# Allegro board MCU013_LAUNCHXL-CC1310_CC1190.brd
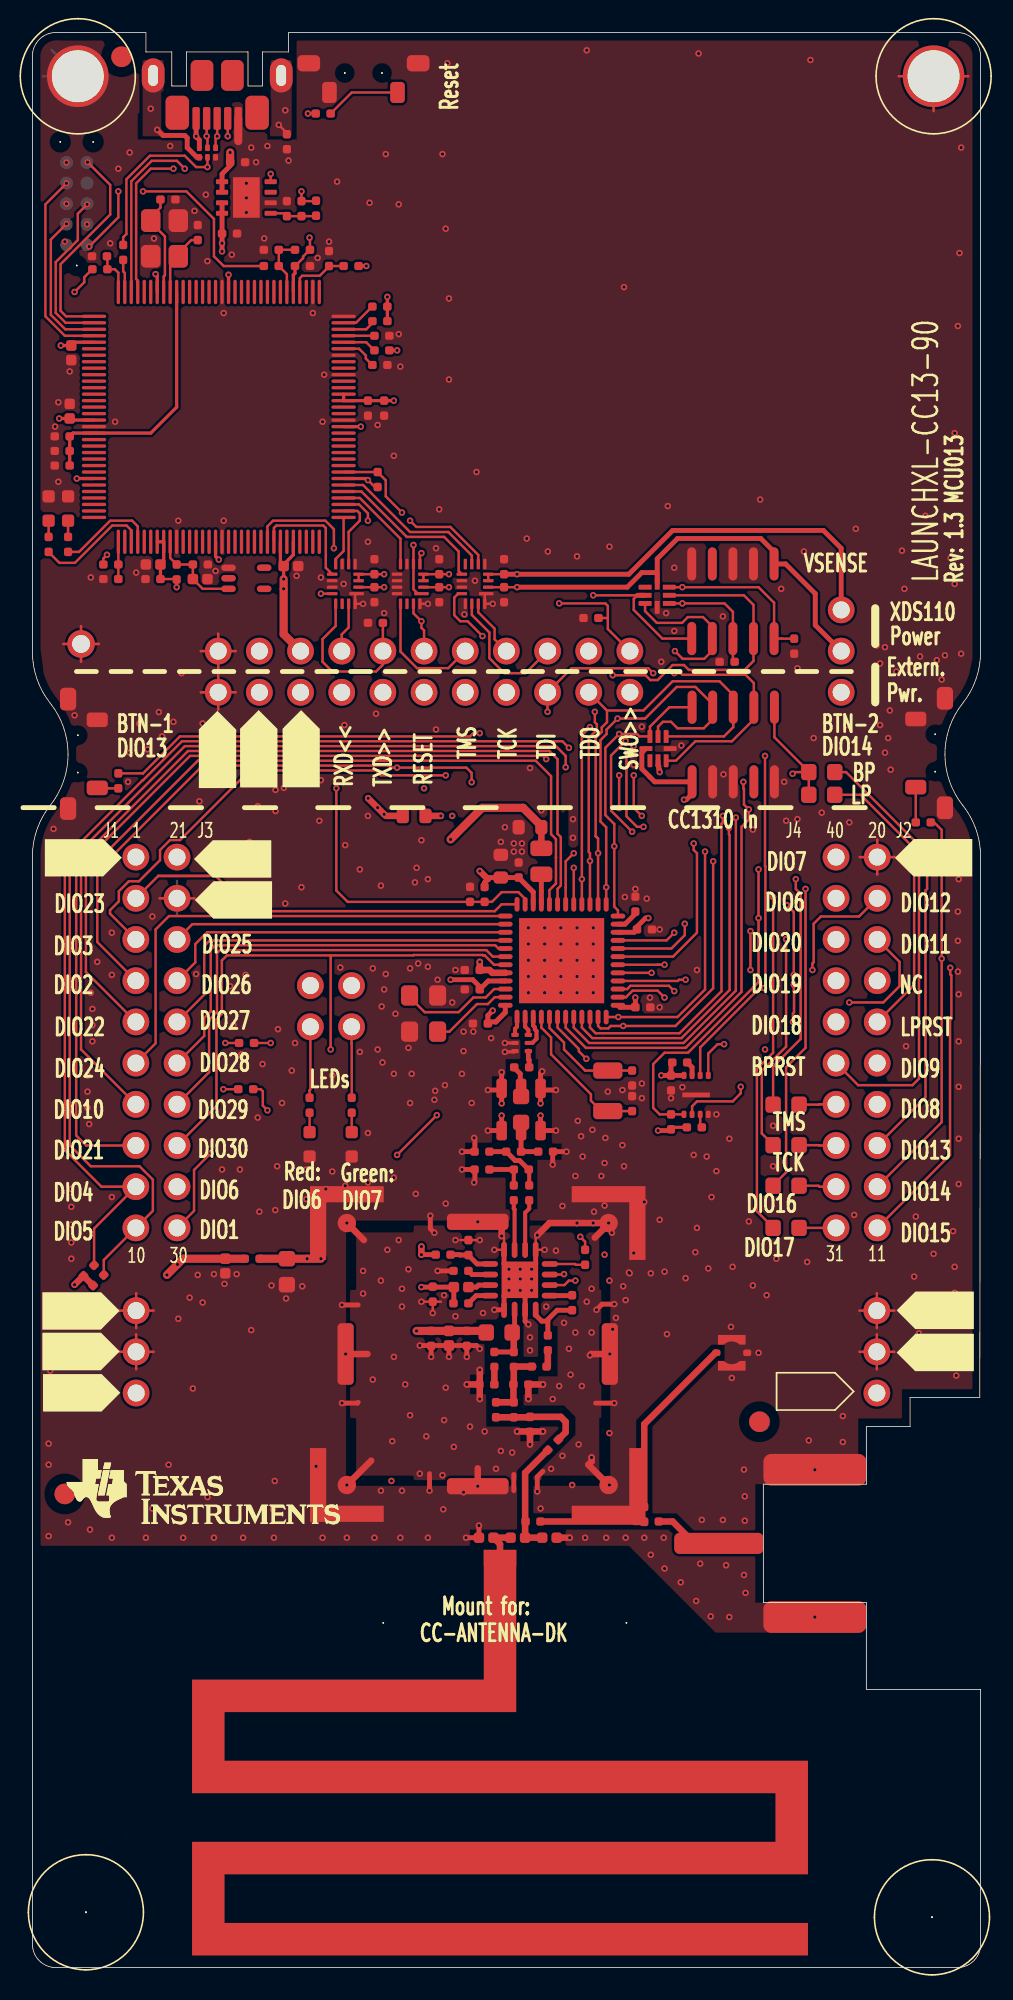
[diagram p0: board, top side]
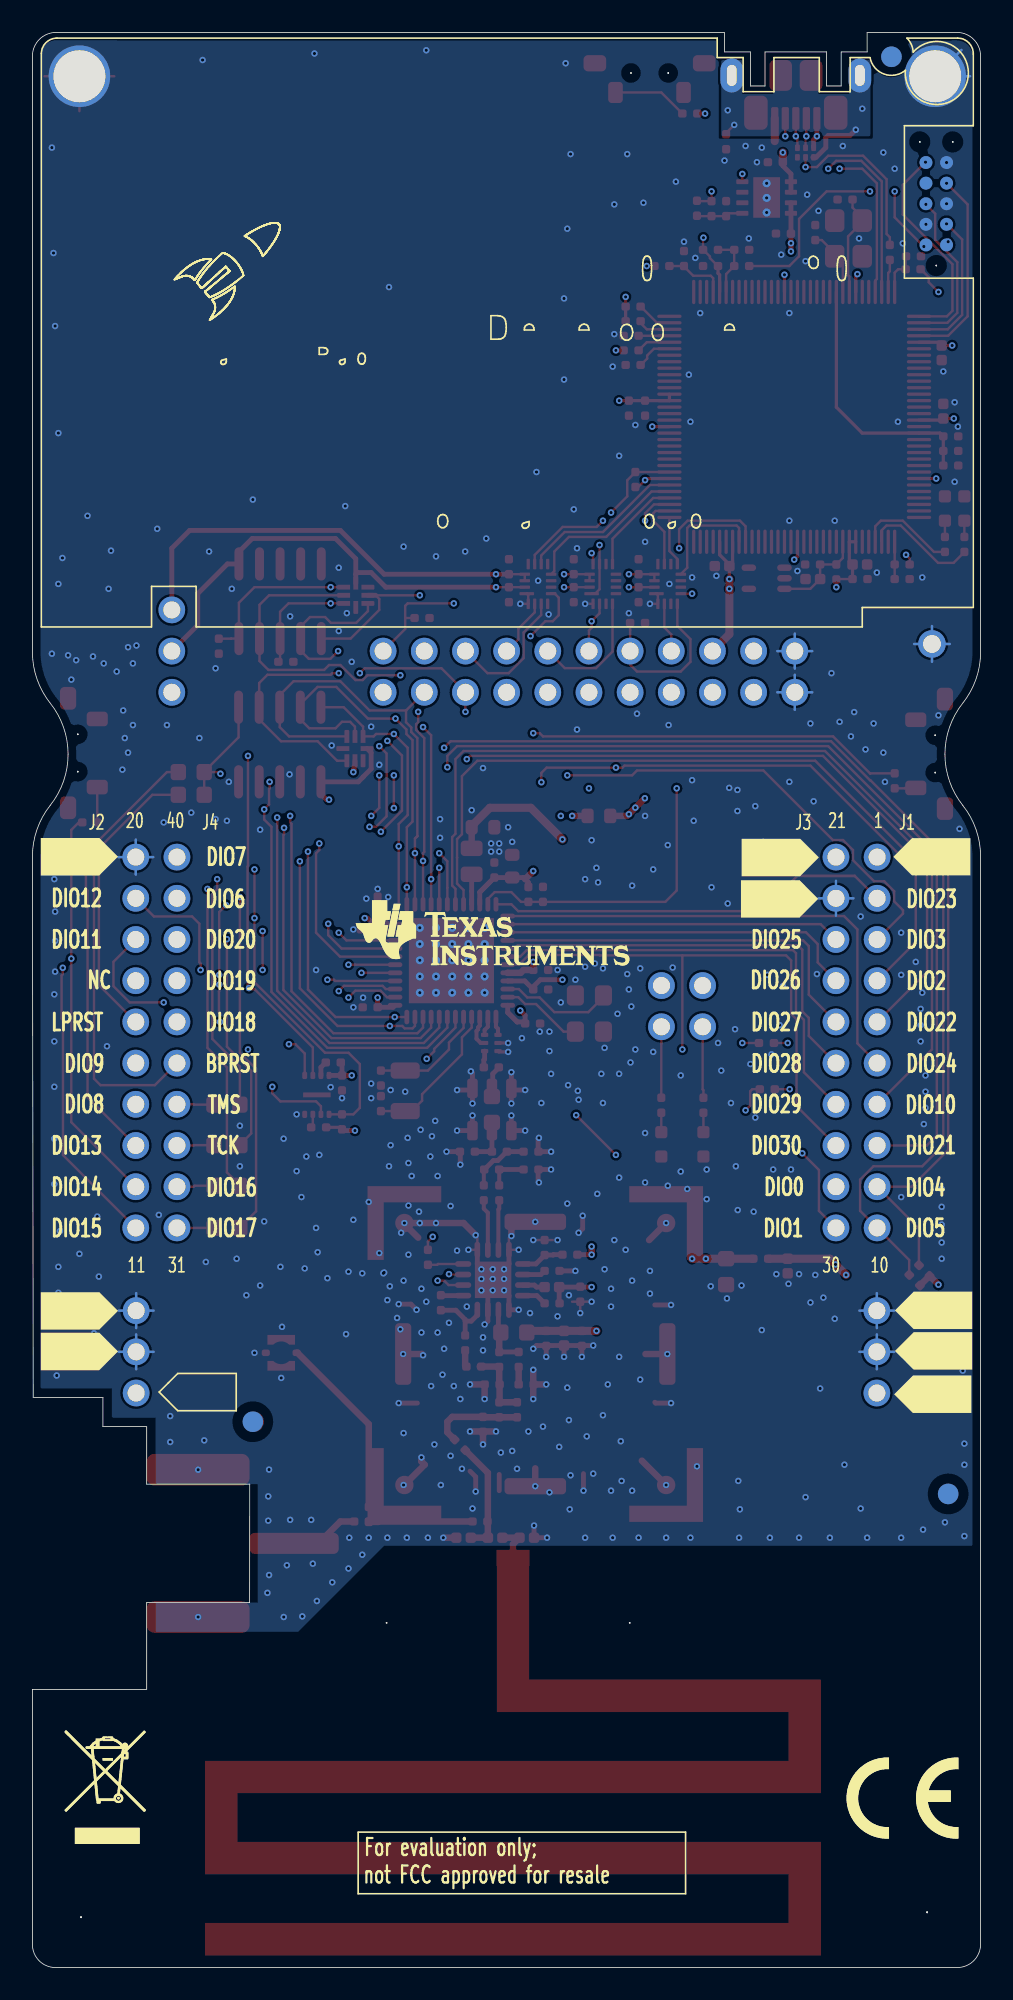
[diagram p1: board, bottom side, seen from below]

Outline 58.5 x 119.3 mm; copper layers: TOP, L2, L3, BOTTOM. Coordinates in mm from the lower left corner of the outline.
Outline path: 0,117.84 0,81.1 arc(0.28,79.43) 1.1,77.95 arc(1.92,76.47) 2.2,74.8 arc(1.92,73.13) 1.1,71.65 arc(0.28,70.17) 0,68.5 0,1.45 arc(0.42,0.42) 1.45,0 57.1,0 arc(58.1,0.44) 58.5,1.45 58.5,17.15 51.45,17.15 51.45,22.5 45.1,22.5 45.09,29.8 51.45,29.8 51.45,33.35 54.15,33.35 54.15,35.15 58.45,35.15 58.5,68.5 arc(58.22,70.17) 57.4,71.65 arc(56.58,73.13) 56.3,74.8 arc(56.58,76.47) 57.4,77.95 arc(58.22,79.43) 58.5,81.1 58.5,117.84 arc(58.07,118.87) 57.04,119.3 15.8,119.3 15.8,118.1 14.2,118.1 14.2,116 13.3,116 13.3,118.1 9.5,118.1 9.5,116 8.6,116 8.6,118.1 7,118.1 7,119.3 1.46,119.3 arc(0.43,118.87) 0,117.84

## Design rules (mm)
constraint set DEFAULT: min track width 0.15

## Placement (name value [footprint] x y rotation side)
A1  DNM  [CAPC1005X60A2N]  31.45 26.5 0 top
A2  1.4pF  [CAPC1005X60A2N]  30.4 26.5 180 top
A3  39nH  [INDC1005X60C2N]  28.45 26.5 180 top
ANT1  868MHz/2440MHz  [ANTENNA_DN024N]  28.85 25.25 180 top
C3  100nF  [CAPC1005X60B2N]  37.2 59.2 0 top
C4  100nF  [CAPC1005X60B2N]  37.3 64 0 top
C5  100nF  [CAPC1005X60B2N]  27.6 61.5 180 top
C6  22uF  [CAPC1608X100A2L]  28.9 67.2 90 top
C7  100nF  [CAPC1005X60B2N]  30 67.2 90 top
C8  22uF  [CAPC1608X100A2L]  31.4 70.3 180 top
C9  100nF  [CAPC1005X60B2N]  28.1 58.2 180 top
C15  100pF  [CAPC1005X60B2N]  30.65 55.5 180 top
C16  100nF  [CAPC1005X60B2N]  27.6 60.3 180 top
C17  12pF  [CAPC1005X60B2N]  37 52.8 90 top
C18  12pF  [CAPC1005X60B2N]  37 55.3 270 top
C19  1uF  [CAPC1005X60B2N]  37.2 65.1 90 top
C20  100nF  [CAPC1005X60B2N]  27 65.7 90 top
C24  2.2pF  [CAPC1005X60B2N]  28.6 34.85 270 top
C25  7.5pF  [CAPC1005X60B2N]  30.7 33.95 270 top
C27  47pF  [CAPC1005X60B2N]  26.8 39.25 270 top
C28  1nF  [CAPC1005X60N]  25.7 39.25 270 top
C29  1uF  [CAPC1005X60B2N]  24.6 39.25 270 top
C30  0.1uF  [CAPC1005X60B2N]  39.4 55 270 top
C32  0.1uF  [CAPC1005X60B2N]  9.9 86.5 0 top
C33  12pF  [CAPC1005X60B2N]  10.2 106.5 90 top
C34  12pF  [CAPC1005X60B2N]  7.9 109 0 top
C35  10nF  [CAPC1005X60N]  15.5 86.4 0 top
C36  10nF  [CAPC1005X60N]  2.3 95.5 90 top
C37  10nF  [CAPC1005X60N]  2.4 100 270 top
C38  0.1uF  [CAPC1005X60B2N]  16.2 104.9 0 top
C39  0.1uF  [CAPC1005X60B2N]  20.7 96.6 270 top
C40  1uF  [CAPC1005X60B2N]  21.7 96.6 270 top
C41  10nF  [CAPC1005X60N]  7.9 86.5 180 top
C42  1uF  [CAPC1005X60B2N]  7.9 85.6 180 top
C43  0.1uF  [CAPC1005X60B2N]  2.3 94.4 180 top
C44  1uF  [CAPC1005X60B2N]  2.3 93.5 180 top
C45  2.2uF  [CAPC1005X60B2N]  2.3 92.6 180 top
C46  0.1uF  [CAPC1005X60B2N]  18.3 104.9 90 top
C47  15pF  [CAPC1005X60B2N]  16.6 108.9 270 top
C48  2.2uF  [CAPC1005X60B2N]  12.2 111.3 0 top
C49  2.2uF  [CAPC1005X60B2N]  11.7 106.9 0 top
C50  10nF  [CAPC1005X60N]  9.9 85.6 0 top
C52  0.1uF  [CAPC1005X60B2N]  21.1 85.9 90 top
C53  0.1uF  [CAPC1005X60B2N]  21.1 85.1 270 top
C54  0.1uF  [CAPC1005X60B2N]  25.1 85.9 90 top
C55  0.1uF  [CAPC1005X60B2N]  25.1 85.1 270 top
C56  0.1uF  [CAPC1005X60B2N]  29.1 85.9 90 top
C57  0.1uF  [CAPC1005X60B2N]  29.1 85.1 270 top
C59  0.1uF  [CAPC1005X60B2N]  4.6 105.5 180 top
C111  0.8pF  [CAPC1005X60B2N]  31.2 50.3 0 top
C131  15pF  [CAPC1005X60B2N]  26.9 44.85 270 top
C161  27pF  [CAPC1005X60B2N]  24.7 41.05 90 top
C210  2.4pF  [CAPC1005X60B2N]  28.5 35.95 180 top
C212  3.3pF  [CAPC1005X60B2N]  30.6 35.95 180 top
C213  12pF  [CAPC1005X60B2N]  33.3 41.45 270 top
C214  12pF  [CAPC1005X60B2N]  31.8 38.05 90 top
C215  47pF  [CAPC1005X60B2N]  29.7 37.95 270 top
C216  220pF  [CAPC1005X60N]  11.9 43.7 270 top
C217  10uF  [CAPC1608X90N]  15.7 43.7 270 top
C218  0  [RESC1005X40B2N]  29.7 47.3 90 top
C219  0  [RESC1005X40B2N]  30.65 47.3 90 top
CR1  LPL296-J2L2-25  [LEDC1707X65L]  19.7 50 90 top
CR2  LS L296-P2Q2-1  [LEDC1708X67L]  17.1 50 90 top
CR4  LS L296-P2Q2-1  [LEDC1708X67L]  1 90.7 270 top
CR5  LPL296-J2L2-25  [LEDC1707X65L]  2.2 90.7 270 top
CR6  TPD4E004DRY  [SON50P100X145X60-6N]  10.3 111.6 0 top
CR7  TPD6E004RSER  [QFN50P150X150X60-8N]  37.8 85.1 270 top
CR8  TPD6E004RSER  [QFN50P150X150X60-8N]  38.1 74.4 0 top
FIDU1  FIDU_1.27mm  [FID127X142]  5.5 117.8 0 top
FIDU2  FIDU_1.27mm  [FID127X142]  2 29.2 0 top
FIDU3  FIDU_1.27mm  [FID127X142]  44.85 33.65 0 top
FIDU4  FIDU_1.27mm  [FID127X142]  5.5 117.8 180 bottom
FIDU5  FIDU_1.27mm  [FID127X142]  2 29.2 180 bottom
FIDU6  FIDU_1.27mm  [FID127X142]  44.9 33.65 180 bottom
FL1  BLM18HE152SN1  [FIL_BLM18HE152SN1DL]  24.25 71 180 top
FL2  B39871B3725U410  [FIL_DCC6CN]  31.35 54.2 180 top
J1  SSQ-110-23-L-D  [SAMTEC_SSQ11023LD_A2B]  6.38 68.46 0 bottom
J2  SSQ-110-23-L-D  [SAMTEC_SSQ11023LD_A2B]  49.58 68.46 0 bottom
J6  105164-0001  [MOLEX_1051640001_A2N]  10.1 114 0 top
L1  6.8uH  [INDC2012X150L]  31.4 67.4 90 top
L21  22nH  [INDC1608X100N]  28 39.15 0 top
L24  9.1nH  [INDC1005X60B2N]  32.45 32.55 225 top
L25  2.4nH  [INDC1005X60D2N]  28.5 37.95 270 top
L26  7.5nH  [INDC1005X60B2N]  30.8 37.05 0 top
L27  2.9nH  [INDC1005X60B2N]  29.7 34.85 270 top
L111  10nH  [INDC1005X60B2N]  30.15 50.3 180 top
L131  1.5nH  [INDC1005X60B2N]  25.8 43.95 180 top
L161  15nH  [INDC1005X60B2N]  26.9 40.95 180 top
L163  11nH  [INDC1005X60B2N]  13.1 43.7 0 top
LBL1  CE_label  [CE_LABEL]  5.65 7.95 180 bottom
LBL4  -  [LABEL_FOR_EVALUATION_ONLY]  38.25 4.7 180 bottom
LBL5  TI_LOGO  [TI_LOGO_1]  3.1 31.35 0 top
LBL6  TRASH_7mm  [TRASH_7MM]  55.88 7.62 180 bottom
M13  SNT-100-BK-G  [SAMTEC_SNT100BKG]  12.65 77.35 90 top
M14  SNT-100-BK-G  [SAMTEC_SNT100BKG]  15.2 77.35 90 top
M15  SNT-100-BK-G  [SAMTEC_SNT100BKG]  17.75 77.35 90 top
M16  SNT-100-BK-G  [SAMTEC_SNT100BKG]  20.3 77.35 90 top
M17  SNT-100-BK-G  [SAMTEC_SNT100BKG]  22.8 77.35 90 top
M18  SNT-100-BK-G  [SAMTEC_SNT100BKG]  25.35 77.35 90 top
M19  SNT-100-BK-G  [SAMTEC_SNT100BKG]  27.9 77.35 90 top
M20  SNT-100-BK-G  [SAMTEC_SNT100BKG]  30.4 77.35 90 top
M21  SNT-100-BK-G  [SAMTEC_SNT100BKG]  32.95 77.35 90 top
M22  SNT-100-BK-G  [SAMTEC_SNT100BKG]  35.5 77.35 90 top
M23  SNT-100-BK-G  [SAMTEC_SNT100BKG]  38.05 77.35 90 top
M24  SNT-100-BK-G  [SAMTEC_SNT100BKG]  51.05 79.9 90 top
M25  SNT-100-BK-G  [SAMTEC_SNT100BKG]  18.35 56.7 90 top
M26  SNT-100-BK-G  [SAMTEC_SNT100BKG]  20.85 56.7 90 top
M27  DCB-10  [MECH_DCB10]  2.8 116.6 0 top
M28  DCB-10  [MECH_DCB10]  3.3 3.41 0 top
M29  DCB-10  [MECH_DCB10]  55.5 3.1 0 top
M30  DCB-10  [MECH_DCB10]  55.6 116.6 0 top
MH1  HOLE_3.2mm_NPL  [MTG320]  3.3 3.4 0 top
MH2  HOLE_3.2mm_NPL  [MTG320]  55.5 3.1 0 top
MH3  HOLE_3.2mm_PTH  [MTG320_380]  2.8 116.6 0 top
MH4  HOLE_3.2mm_PTH  [MTG320_380]  55.6 116.6 0 top
MH5  HOLE_1.1mm_PTH  [MTG110_170]  3 81.6 0 top
NOREF  -  []  8.3 65.8 0 top
NOREF#2  -  []  -154.03 -148.09 0 top
NOREF#3  -  []  0 113.92 0 top
NOREF#4  -  []  0.7 67.2 0 top
NOREF#5  -  []  -1.8 32.9 0 top
NOREF#6  -  []  13.8 70.4 90 top
NOREF#7  -  []  51.6 35.5 0 top
NOREF#8  -  []  8.3 63.4 0 top
NOREF#9  -  []  51.6 38.1 0 top
NOREF#10  -  []  -1.7 35.6 0 top
NOREF#11  -  []  17.8 72.7 90 top
NOREF#12  -  []  45.1 25.98 0 top
NOREF#13  #VALUE  [unnamed#2]  21.65 21.25 0 top
NOREF#14  -  []  -1.7 38.1 0 top
NOREF#15  -  []  51.5 66 0 top
NOREF#16  -  []  46.53 0 90 top
NOREF#17  -  []  28.8 117.9 0 top
NOREF#18  -  []  0.76 119.12 0 top
NOREF#19  -  []  55.4 17.15 90 top
NOREF#20  -  []  11.37 118.1 0 top
NOREF#21  -  []  16.5 70.3 90 top
NOREF#22  -  []  60.3 66.1 180 bottom
NOREF#23  -  []  7 38.1 180 bottom
NOREF#24  -  []  51.53 89.52 180 bottom
NOREF#25  -  []  37.55 65.8 180 bottom
NOREF#26  -  []  5.6 67.1 180 bottom
NOREF#27  -  []  60.3 35.6 180 bottom
NOREF#28  -  []  7 32.8 180 bottom
NOREF#29  -  []  17.1 63.5 180 bottom
NOREF#30  -  []  17.2 65.9 180 bottom
NOREF#31  -  []  60.3 38.1 180 bottom
NOREF#32  -  []  7 35.6 180 bottom
P1  BB02-HC031-KB1-603000  [GRADCONN_BB02HC031KB1603000_A2B]  52.1 35.42 90 top
P2  BB02-HC031-KB1-603000  [GRADCONN_BB02HC031KB1603000_A2B]  6.4 35.42 90 top
P4  BB02-HJ221-KB1-603000  [GRADCONN_BB02HJ221KB160300_A2B]  36.86 81.16 180 top
P5  FTSH-105-01-F-DV-K  [SAMTEC_FTSH-105-01-F-DV-K-10L]  40.7 73.1 0 top
P6  BB02-HJ041-KB1-603000  [GRADCONN_BB02HJ041KB1603000_A2B]  17.15 58 0 top
P7  FTSH-105-01-F-DV-K  [SAMTEC_FTSH-105-01-F-DV-K-10L]  45.76 86.53 180 top
P8  TC2050-IDC-NL  [TAGCONNECT_TC2050IDCNLN]  2.1 106.2 90 bottom
P10  BB02-HC031-KB1-603000  [GRADCONN_BB02HC031KB1603000_A2B]  49.9 83.7 270 top
P11  MM5829-2700  [MURATA_MM58292700RJ4_A2N]  42.2 37.9 0 top
P12  142-0721-88  [CINCH_1420721882_A2N]  42.35 26.15 0 top
R1  100k  [RESC1005X40B2N]  27.9 65.7 90 top
R2  3.3k  [RESC1005X40B2N]  3.8 43.3 225 top
R3  3.3k  [RESC1005X40B2N]  4.4 42.7 225 top
R11  2.2k  [RESC1005X40B2N]  39.4 52.6 270 top
R13  0  [RESC1005X40B2N]  38.65 27.5 180 top
R14  220  [RESC1005X40B2N]  17.1 52.7 90 top
R15  180  [RESC1005X40B2N]  19.7 52.7 90 top
R17  10k  [RESC1005X40B2N]  16.2 105.9 0 top
R18  4.7k  [RESC1005X40B2N]  8.9 86.5 270 top
R19  DNM  [RESC1005X40B2N]  5.6 106.2 270 top
R20  100  [RESC1005X40B2N]  15.2 104.9 180 top
R21  DNM  [RESC1005X40B2N]  15.2 105.9 180 top
R22  330k  [RESC1005X40B2N]  5.3 86.5 180 top
R23  180  [RESC1005X40B2N]  1 88.2 270 top
R24  220k  [RESC1005X40B2N]  5.3 85.6 180 top
R25  220  [RESC1005X40B2N]  2.2 88.2 270 top
R27  1k  [RESC1005X40B2N]  21.9 101.5 180 top
R28  4.87k  [RESC1005X40B2N]  21.9 98.8 180 top
R29  1k  [RESC1005X40B2N]  21.1 100.6 0 top
R30  1k  [RESC1005X40B2N]  21.1 99.7 0 top
R31  51  [RESC1005X40B2N]  19.2 104.9 0 top
R32  33k  [RESC1005X40B2N]  15.7 112.1 90 top
R33  51k  [RESC1005X40B2N]  17.5 108 90 top
R34  30k  [RESC1005X40B2N]  15.7 108.9 270 top
R39  1k  [RESC1005X40B2N]  21.9 102.4 180 top
R46  DNM  [RESC1608X55N]  47.3 53.2 180 top
R47  DNM  [RESC1608X55N]  47.3 50.7 180 top
R48  DNM  [RESC1608X55N]  47.3 48.2 180 top
R49  DNM  [RESC1608X55N]  47.3 45.6 180 top
R51  DNM  [RESC1608X55N]  49.5 72.3 180 top
R52  0  [RESC1608X55N]  47.9 73.7 0 top
R55  100  [RESC1005X40B2N]  54.5 70.6 0 top
R56  100  [RESC1005X40B2N]  5.3 72.7 90 top
R57  100  [RESC1005X40B2N]  18.4 114.3 180 top
R58  3.3k  [RESC1005X40B2N]  21.3 92.2 270 top
R59  DNM  [RESC1005X40B2N]  41.3 51.8 180 top
R60  DNM  [RESC1005X40B2N]  40.4 55.8 180 top
R61  100k  [RESC1005X40B2N]  20.7 82.9 0 top
R62  100k  [RESC1005X40B2N]  34 83.2 0 top
R63  100k  [RESC1005X40B2N]  42.4 80.5 0 top
R65  100k  [RESC1005X40B2N]  47 81 90 top
R66  10k  [RESC1005X40B2N]  12.75 57 0 top
R71  10k  [RESC1005X40B2N]  12.7 54.15 0 top
R81  10k  [RESC1005X40B2N]  34.1 44.25 270 top
R141  3.3k  [RESC1005X40B2N]  26.9 42.95 180 top
R151  47  [RESC1005X40N]  26 41.95 0 top
R152  100  [RESC1005X40B2N]  3.7 104.7 0 top
R153  DNM  [RESC1608X55N]  30.15 52.1 90 top
R154  0  [RESC1005X40B2N]  29.7 49.2 0 top
R155  DNM  [RESC1005X40B2N]  28.2 50.3 180 top
R156  DNM  [RESC1005X40B2N]  28.2 49.2 180 top
R157  DNM  [RESC1005X40B2N]  37.75 28.4 270 top
R158  DNM  [RESC1005X40B2N]  31.35 27.5 180 top
SC1  BMIS-202  [MECH_BMIS202N]  19.4 29.75 0 top
SW1  1188E-1K2-V  [SW_1188E1K2V_A2N]  2.2 78.2 270 top
SW2  1188E-1K2-V  [SW_1188E1K2V_A2N]  56.3 71.5 90 top
SW3  1188E-1K2-V  [SW_1188E1K2V_A2N]  23.8 117.4 180 top
TR1  0850BM14E0016  [XFMR_0850BM14E0016_A2N]  30.6 56.5 90 top
U1  CC1310F128RGZ  [QFNFC50P700X700X80-49CN]  29.9 58.6 0 top
U4  MX25R8035FZUIL0  [SON50P300X200X60-9B2L]  40.2 52.6 0 top
U5  TM4C1294NCPDTT3R  [QFP40P1600X1600X120-128N]  5.3 87.9 0 top
U6  LM4040B25IDCK  [SOT65P210X110-5N]  12.1 86.3 270 top
U7  TPS79601DR  [SON65P300X300X100-9AL]  11.7 110.1 270 top
U8  SN74AVC4T245RSV  [QFNFC40P180X260X55-16A2L]  20 84.7 90 top
U9  SN74AVC4T245RSV  [QFNFC40P180X260X55-16A2L]  28 84.7 90 top
U10  SN74AVC4T245RSV  [QFNFC40P180X260X55-16A2L]  24 84.7 90 top
U11  CC1190  [QFNFC65P400X400X100-17AN]  29.1 40.55 0 top
Y1  32.768kHz  [XTAL_FC-135N]  35.5 52.8 90 top
Y2  24MHz  [OSCCC250X320X60-4L]  25 57.7 90 top
Y3  16MHz  [OSCCC250X320X100-4BN]  9 105.5 90 top

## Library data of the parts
A1 A2 = CAPACITOR: User Part Number: #PN; alternate symbols: (CAPC1005X60A2L,CAPC1005X60A2M)
A3 = INDUCTOR_HOR_1_2: User Part Number: #PN; alternate symbols: (INDC1005X60C2L,INDC1005X60C2M)
ANT1 = ANTENNA_PCB: User Part Number: #PN
C3-C5 C7 C9 C15-C20 C24 C25 C27 C29 C30 C32-C34 C38-C40 C42-C49 C52-C57 C59 C111 C131 C161 C210 C212-C215 = CAPACITOR: User Part Number: #PN
C6 C8 = CAPACITOR: User Part Number: #PN; alternate symbols: (CAPC1608X100A2L,CAPC1608X100A2M)
C28 C35-C37 C41 C50 C216 = CAPACITOR: User Part Number: #PN; alternate symbols: (CAPC1005X60L,CAPC1005X60M)
C217 = CAPACITOR: alternate symbols: (CAPC1608X90L,CAPC1608X90M)
C218 C219 R1-R3 R11 R13-R15 R17-R25 R27-R34 R39 R55-R63 R65 R66 R71 R81 R141 R152 R154-R158 = RESISTOR: User Part Number: #PN
CR1 CR5 = LED: alternate symbols: (LEDC1707X65L,LEDC1707X65M)
CR2 CR4 = LED: alternate symbols: (LEDC1708X67L,LEDC1708X67M)
CR6 = DIODE_TPD4E004_SON6: User Part Number: #PN; alternate symbols: (SON50P100X145X65-6L,SON50P100X145X65-6M)
CR7 CR8 = DIODE_TVS_TPD6E004_QFN8: alternate symbols: (QFN50P150X150X60-8L,QFN50P150X150X60-8M,QFN50P150X150X60-8AL,QFN50P150X150X60-8AM)
FIDU1-FIDU6 = FIDMARK
FL1 = FILTER_2PIN: alternate symbols: (FIL_BLM18HE152SN1DL,FIL_BLM18HE152SN1DM)
FL2 = FILTER_SAW_RF_B3: alternate symbols: (FIL_DCC6CL,FIL_DCC6CM)
J1 J2 = CONN_HEADER_2X10_J_S_V1: User Part Number: #PN; alternate symbols: (SAMTEC_SSQ11023LD_A2C,SAMTEC_SSQ11023LD_A2A)
J6 = CONN_USB_MICRO_B_2MH: User Part Number: #PN; alternate symbols: (MOLEX_1051640001_A2L,MOLEX_1051640001_A2M)
L1 = INDUCTOR: alternate symbols: (INDC2012X150L,INDC2012X150M)
L21 = INDUCTOR: alternate symbols: (INDC1608X100L,INDC1608X100M)
L24 L26 L27 L111 L131 L161 L163 = INDUCTOR: User Part Number: #PN
L25 = INDUCTOR_HOR_1_2: User Part Number: #PN
LBL1 = CE_LABEL
LBL4 = LABEL_FOR_EVALUATOIN_ONLY: User Part Number: #PN
LBL5 = TI_LOGO_V1
LBL6 = TRASH_V2: User Part Number: #PN
M13-M26 = MECH_SHUNT_JUMPER_V1: User Part Number: #PN
M27-M30 = MECH_SPACERS_SUPPORT_V1: User Part Number: #PN
MH1 MH2 = HOLE_NPL
MH3-MH5 = HOLE_PTH
NOREF#13 = -: User Part Number: #PN
P1 P2 P10 = CONN_HEADER_3_P_S: User Part Number: #PN; alternate symbols: (GRADCONN_BB02HC031KB1603000_A2C,GRADCONN_BB02HC031KB1603000_A2A)
P4 = CONN_HEADER_2X11_P_S: User Part Number: #PN; alternate symbols: (GRADCONN_BB02HJ221KB160300_A2C,GRADCONN_BB02HJ221KB160300_A2A)
P5 P7 = CONN_HEADER_2X5: alternate symbols: (SAMTEC_FTSH-105-01-F-DV-K-10L,SAMTEC_FTSH-105-01-F-DV-K-10M)
P6 = CONN_HEADER_2X2_P: User Part Number: #PN; alternate symbols: (GRADCONN_BB02HJ041KB1603000_A2C,GRADCONN_BB02HJ041KB1603000_A2A)
P8 = CONN_IDC_TC2050-IDC-NL: User Part Number: #PN; alternate symbols: (TAGCONNECT_TC2050IDCNLL,TAGCONNECT_TC2050IDCNLM)
P11 = CONN_COAX_1_1_P_2MH: User Part Number: #PN; alternate symbols: (MURATA_MM58292700RJ4_A2L,MURATA_MM58292700RJ4_A2M)
P12 = CONN_COAX_1_J_2MH: User Part Number: #PN
R46-R49 R51 R52 R153 = RESISTOR: alternate symbols: (RESC1608X55L,RESC1608X55M)
R151 = RESISTOR: User Part Number: #PN; alternate symbols: (RESC1005X40L,RESC1005X40M)
SC1 = SHIELD_COVER_BMIS-202
SW1-SW3 = SWITCH_TACT_V2: alternate symbols: (SW_1188E1K2V_A2L,SW_1188E1K2V_A2M)
TR1 = XFMR_0850BM14E0016T: alternate symbols: (XFMR_0850BM14E0016_A2L,XFMR_0850BM14E0016_A2M)
U1 = IC_RF_CC13XX_7X7_QFN48_V2: alternate symbols: (QFNFC50P700X700X100-49A2L,QFNFC50P700X700X100-49A2M)
U4 = IC_FLASH_MX25R8035F_USON8: User Part Number: #PN; alternate symbols: (SON50P300X200X60-9B2L,SON50P300X200X60-9B2M)
U5 = IC_PROC_TM4C1294NCPDT_TQFP128: alternate symbols: (QFP40P1600X1600X120-128L,QFP40P1600X1600X120-128M)
U6 = IC_REF_LM4040_SC70-5: alternate symbols: (SOT65P210X110-5L,SOT65P210X110-5M)
U7 = IC_PM_TPS79601_SON8: alternate symbols: (SON65P300X300X100-9AL,SON65P300X300X100-9AM)
U8-U10 = IC_XCVR_SN74AVC4T245_UQFN16_2: User Part Number: #PN; alternate symbols: (QFNFC40P180X260X55-16A2L,QFNFC40P180X260X55-16A2M)
U11 = IC_RF_CC1190_QFN16: alternate symbols: (QFNFC65P400X400X100-17AL,QFNFC65P400X400X100-17AM)
Y1 = CRYSTAL: alternate symbols: (XTAL_FC-135L,XTAL_FC-135M)
Y2 = XTAL_4PIN_S: alternate symbols: (OSCCC250X320X60-4L,OSCCC250X320X60-4M)
Y3 = XTAL_4: alternate symbols: (OSCCC250X320X100-4BL,OSCCC250X320X100-4BM)

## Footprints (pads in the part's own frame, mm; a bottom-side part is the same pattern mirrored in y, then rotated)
ANTENNA_DN024N
  rect 2x1 smd: 1(0,0)
CAPC1005X60A2N
  custom 0.16x0.16 smd: 1(0,0) 2(0.9,0)
CAPC1005X60B2N
  custom 0.125x0.125 smd: 1(0,0) 2(0.924,0)
CAPC1005X60N
  custom 0.16x0.16 smd: 1(0,0) 2(0.9,0)
CAPC1608X90N
  custom 0.237x0.237 smd: 1(0,0) 2(1.6,0)
CAPC1608X100A2L
  custom 0.188x0.188 smd: 1(0,0) 2(1.4,0)
CE_LABEL
  oval 0.025x0.051 smd: 1(-0.15,0.1)
CINCH_1420721882_A2N
  custom 0.325x0.325 smd: 1(0,0)
  custom 0.487x0.487 smd: M1(5.925,-4.54) M2(5.925,4.54)
FID127X142
  round 1.27 smd: 1(0,0)
FIL_BLM18HE152SN1DL
  custom 0.188x0.188 smd: 1(0,0) 2(1.4,0)
FIL_DCC6CN
  custom 0.163x0.163 smd: 1(0,0) 2(1.2,0) 3(2.4,0) 4(2.4,2.6) 5(1.2,2.6) 6(0,2.6)
GRADCONN_BB02HC031KB1603000_A2B
  round 1.65 hole 1.05: 1(0,0) 2(2.54,0) 3(5.08,0)
GRADCONN_BB02HJ041KB1603000_A2B
  round 1.65 hole 1.05: 1(0,0) 2(0,2.54) 3(2.54,0) 4(2.54,2.54)
GRADCONN_BB02HJ221KB160300_A2B
  round 1.65 hole 1.05: 1(0,0) 2(0,2.54) 3(2.54,0) 4(2.54,2.54) 5(5.08,0) 6(5.08,2.54) 7(7.62,0) 8(7.62,2.54) 9(10.16,0) 10(10.16,2.54) 11(12.7,0) 12(12.7,2.54) 13(15.24,0) 14(15.24,2.54) 15(17.78,0) 16(17.78,2.54) 17(20.32,0) 18(20.32,2.54) 19(22.86,0) 20(22.86,2.54) 21(25.4,0) 22(25.4,2.54)
INDC1005X60B2N
  custom 0.125x0.125 smd: 1(0,0) 2(0.924,0)
INDC1005X60C2N
  custom 0.16x0.16 smd: 1(0,0) 2(0.9,0)
INDC1005X60D2N
  custom 0.125x0.125 smd: 1(0,0) 2(0.924,0)
INDC1608X100N
  custom 0.237x0.237 smd: 1(0,0) 2(1.6,0)
INDC2012X150L
  custom 0.237x0.237 smd: 1(0,0) 2(1.6,0)
LEDC1707X65L
  custom 0.188x0.188 smd: 1(0,0) 2(1.501,0)
LEDC1708X67L
  custom 0.188x0.188 smd: 1(0,0) 2(1.501,0)
MECH_BMIS202N
  custom 1.137x1.137 smd: 1(0,0) 3(16.15,0) 5(16.15,16.15) 7(0,16.15)
  custom 0.25x0.25 smd: 2(8.075,-0.075) 4(16.225,8.075) 6(8.075,16.225) 8(-0.075,8.075)
MECH_DCB10
  round 0.1 hole 3 unplated: (0,0)
MOLEX_1051640001_A2N
  custom 0.362x0.362 smd: (-1.162,0.35) (3.762,0.35)
  custom 0.35x0.35 smd: (0.362,2.65) (2.238,2.65)
  custom 0.113x0.113 smd: 1(0,0) 2(0.65,0) 3(1.3,0) 4(1.95,0) 5(2.6,0)
  oval 1.4x2.1 hole 0.6x1.3: M1(-2.65,2.65) M2(5.25,2.65)
MTG110_170
  round 1.699 hole 1.1: 1(0,0)
MTG320
  round 0.099 hole 3.2 unplated: (0,0)
MTG320_380
  round 3.8 hole 3.2: 1(0,0)
MURATA_MM58292700RJ4_A2N
  custom 0.1x0.1 smd: 1(0,0) 2(1.9,0)
  custom 0.15x0.15 smd: M1(0.95,-0.8) M2(0.95,0.8)
OSCCC250X320X60-4L
  custom 0.263x0.263 smd: 1(0,0) 2(2.23,0) 3(2.23,1.73) 4(0,1.73)
OSCCC250X320X100-4BN
  custom 0.299x0.299 smd: 1(0,0) 2(2.2,0) 3(2.2,1.699) 4(0,1.699)
QFN50P150X150X60-8N
  custom 0.075x0.075 smd: 1(0,0) 2(0.5,0) 3(1,0) 4(1.25,0.75) 5(1,1.5) 6(0.5,1.5) 7(0,1.5) 8(-0.25,0.75)
QFNFC40P180X260X55-16A2L
  custom 0.05x0.05 smd: 1(0,0) 2(0.4,-0.125) 3(0.8,-0.125) 4(1.2,-0.125) 5(1.825,0.09) 6(1.825,0.49) 7(1.825,0.89) 8(1.825,1.29) 9(1.2,1.505) 10(0.8,1.505) 11(0.4,1.505) 12(0,1.505) 13(-0.625,1.29) 14(-0.625,0.89) 15(-0.625,0.49) 16(-0.625,0.09)
QFNFC50P700X700X80-49CN
  oval 0.3x0.9 smd: 1(0,0) 2(0.5,0) 3(1,0) 4(1.5,0) 5(2,0) 6(2.5,0) 7(3,0) 8(3.5,0) 9(4,0) 10(4.5,0) 11(5,0) 12(5.5,0) 25(5.5,6.95) 26(5,6.95) 27(4.5,6.95) 28(4,6.95) 29(3.5,6.95) 30(3,6.95) 31(2.5,6.95) 32(2,6.95) 33(1.5,6.95) 34(1,6.95) 35(0.5,6.95) 36(0,6.95)
  oval 0.9x0.3 smd: 13(6.225,0.725) 14(6.225,1.225) 15(6.225,1.725) 16(6.225,2.225) 17(6.225,2.725) 18(6.225,3.225) 19(6.225,3.725) 20(6.225,4.225) 21(6.225,4.725) 22(6.225,5.225) 23(6.225,5.725) 24(6.225,6.225) 37(-0.725,6.225) 38(-0.725,5.725) 39(-0.725,5.225) 40(-0.725,4.725) 41(-0.725,4.225) 42(-0.725,3.725) 43(-0.725,3.225) 44(-0.725,2.725) 45(-0.725,2.225) 46(-0.725,1.725) 47(-0.725,1.225) 48(-0.725,0.725)
  rect 5.25x5.25 smd: 49(2.75,3.475)
QFNFC65P400X400X100-17AN
  oval 0.35x1 smd: 1(0,0) 2(0.65,0) 3(1.3,0) 4(1.95,0) 9(1.95,3.7) 10(1.3,3.7) 11(0.65,3.7) 12(0,3.7)
  oval 1x0.35 smd: 5(2.825,0.875) 6(2.825,1.525) 7(2.825,2.175) 8(2.825,2.825) 13(-0.875,2.825) 14(-0.875,2.175) 15(-0.875,1.525) 16(-0.875,0.875)
  rect 2.25x2.25 smd: 17(0.975,1.85)
QFP40P1600X1600X120-128N
  oval 0.201x1.501 smd: 1(0,0) 2(0.399,0) 3(0.8,0) 4(1.199,0) 5(1.6,0) 6(1.999,0) 7(2.4,0) 8(2.799,0) 9(3.2,0) 10(3.599,0) 11(4,0) 12(4.399,0) 13(4.801,0) 14(5.199,0) 15(5.601,0) 16(6,0) 17(6.401,0) 18(6.8,0) 19(7.201,0) 20(7.6,0) 21(8.001,0) 22(8.4,0) 23(8.801,0) 24(9.2,0) 25(9.601,0) 26(10,0) 27(10.399,0) 28(10.8,0) 29(11.199,0) 30(11.6,0) 31(11.999,0) 32(12.4,0) 65(12.4,15.4) 66(11.999,15.4) 67(11.6,15.4) 68(11.199,15.4) 69(10.8,15.4) 70(10.399,15.4) 71(10,15.4) 72(9.601,15.4) 73(9.2,15.4) 74(8.801,15.4) 75(8.4,15.4) 76(8.001,15.4) 77(7.6,15.4) 78(7.201,15.4) 79(6.8,15.4) 80(6.401,15.4) 81(6,15.4) 82(5.601,15.4) 83(5.199,15.4) 84(4.801,15.4) 85(4.399,15.4) 86(4,15.4) 87(3.599,15.4) 88(3.2,15.4) 89(2.799,15.4) 90(2.4,15.4) 91(1.999,15.4) 92(1.6,15.4) 93(1.199,15.4) 94(0.8,15.4) 95(0.399,15.4) 96(0,15.4)
  oval 1.501x0.201 smd: 33(13.899,1.501) 34(13.899,1.9) 35(13.899,2.301) 36(13.899,2.7) 37(13.899,3.099) 38(13.899,3.5) 39(13.899,3.899) 40(13.899,4.3) 41(13.899,4.699) 42(13.899,5.1) 43(13.899,5.499) 44(13.899,5.9) 45(13.899,6.299) 46(13.899,6.7) 47(13.899,7.099) 48(13.899,7.501) 49(13.899,7.899) 50(13.899,8.301) 51(13.899,8.7) 52(13.899,9.101) 53(13.899,9.5) 54(13.899,9.901) 55(13.899,10.3) 56(13.899,10.701) 57(13.899,11.1) 58(13.899,11.501) 59(13.899,11.9) 60(13.899,12.301) 61(13.899,12.7) 62(13.899,13.099) 63(13.899,13.5) 64(13.899,13.899) 97(-1.501,13.899) 98(-1.501,13.5) 99(-1.501,13.099) 100(-1.501,12.7) 101(-1.501,12.301) 102(-1.501,11.9) 103(-1.501,11.501) 104(-1.501,11.1) 105(-1.501,10.701) 106(-1.501,10.3) 107(-1.501,9.901) 108(-1.501,9.5) 109(-1.501,9.101) 110(-1.501,8.7) 111(-1.501,8.301) 112(-1.501,7.899) 113(-1.501,7.501) 114(-1.501,7.099) 115(-1.501,6.7) 116(-1.501,6.299) 117(-1.501,5.9) 118(-1.501,5.499) 119(-1.501,5.1) 120(-1.501,4.699) 121(-1.501,4.3) 122(-1.501,3.899) 123(-1.501,3.5) 124(-1.501,3.099) 125(-1.501,2.7) 126(-1.501,2.301) 127(-1.501,1.9) 128(-1.501,1.501)
RESC1005X40B2N
  custom 0.125x0.125 smd: 1(0,0) 2(0.924,0)
RESC1005X40N
  custom 0.16x0.16 smd: 1(0,0) 2(0.9,0)
RESC1608X55N
  custom 0.237x0.237 smd: 1(0,0) 2(1.6,0)
SAMTEC_FTSH-105-01-F-DV-K-10L
  oval 0.551x2.05 smd: 1(0,0) 2(0,4.6) 3(1.27,0) 4(1.27,4.6) 5(2.54,0) 6(2.54,4.6) 7(3.81,0) 8(3.81,4.6) 9(5.08,0) 10(5.08,4.6)
SAMTEC_SSQ11023LD_A2B
  round 1.65 hole 1.05: 1(0,0) 2(2.54,0) 3(0,2.54) 4(2.54,2.54) 5(0,5.08) 6(2.54,5.08) 7(0,7.62) 8(2.54,7.62) 9(0,10.16) 10(2.54,10.16) 11(0,12.7) 12(2.54,12.7) 13(0,15.24) 14(2.54,15.24) 15(0,17.78) 16(2.54,17.78) 17(0,20.32) 18(2.54,20.32) 19(0,22.86) 20(2.54,22.86)
SON50P100X145X60-6N
  custom 0.075x0.075 smd: 1(0,0) 2(0.5,0) 3(1.001,0) 4(1.001,0.589) 5(0.5,0.589) 6(0,0.589)
SON50P300X200X60-9B2L
  custom 0.075x0.075 smd: 1(0,0) 2(0.5,0) 3(1,0) 4(1.5,0) 5(1.5,2.4) 6(1,2.4) 7(0.5,2.4) 8(0,2.4)
  rect 1.7x0.3 smd: 9(0.75,1.2)
SON65P300X300X100-9AL
  custom 0.075x0.075 smd: 1(0,0) 2(0.65,0) 3(1.3,0) 4(1.95,0) 5(1.95,3) 6(1.3,3) 7(0.65,3) 8(0,3)
  rect 2.5x1.65 smd: 9(0.975,1.5)
SOT65P210X110-5N
  oval 0.399x0.899 smd: 1(0,0) 2(0.65,0) 3(1.3,0) 4(1.3,2.2) 5(0,2.2)
SW_1188E1K2V_A2N
  round 0.099 hole 0.899 unplated: (2.229,0.6) (4.529,0.6)
  custom 0.25x0.25 smd: 1(0,0) 2(6.75,0)
  custom 0.225x0.225 smd: 3(1.275,1.8) 4(5.475,1.8)
TAGCONNECT_TC2050IDCNLN
  round 0.099 hole 1.001 unplated: (-1.27,0.635) (6.35,-0.38) (6.35,1.65)
  round 0.8 smd: 1(0,0) 2(1.27,0) 3(2.54,0) 4(3.81,0) 5(5.08,0) 6(5.08,1.27) 7(3.81,1.27) 8(2.54,1.27) 9(1.27,1.27) 10(0,1.27)
unnamed#2
  round 0.099 hole 3.2 unplated: (0,0) (15,0)
XFMR_0850BM14E0016_A2N
  custom 0.062x0.062 smd: 1(0,0) 2(0.5,0) 3(1,0) 4(1,0.825) 5(0.5,0.825) 6(0,0.825)
XTAL_FC-135N
  custom 0.25x0.25 smd: 1(0,0) 2(2.499,0)

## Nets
+5V: J1.2 P2.1 P4.20
GND: A1.2 A3.2 C3.2 C4.2 C5.2 C6.2 C7.2 C8.2 C9.2 C16.2 C17.2 C18.2 C19.2 C20.2 C25.2 C27.2 C28.2 C29.2 C30.2 C32.2 C33.2 C34.2 C35.2 C36.2 C37.2 C38.2 C39.2 C40.2 C41.2 C42.2 C43.2 C44.2 C45.2 C46.2 C48.2 C49.2 C50.2 C52.2 C53.2 C54.2 C55.2 C56.2 C57.2 C59.2 C111.2 C131.1 C161.1 C210.2 C212.1 C216.2 C217.2 CR1.1(C) CR2.1(C) CR4.1(C) CR5.1(C) CR6.3 CR7.4 CR8.4 FL2.1 FL2.3 FL2.4 FL2.6 J1.4 J2.2 J6.5 MH3.1 MH4.1 MH5.1 P1.2 P1.3 P2.2 P2.3 P4.21 P4.22 P5.3 P5.5 P5.9 P7.3 P7.5 P7.9 P8.3 P8.5 P8.9 P11.2 P11.M1 P11.M2 P12.M1 P12.M2 R21.2 R24.2 R28.1 R29.2 R32.1 R34.1 R61.1 R62.1 R63.1 R65.1 R141.2 R155.2 R156.2 SC1.1 SC1.2 SC1.3 SC1.4 SC1.5 SC1.6 SC1.7 SC1.8(GND#8) SW1.1 SW1.2 SW1.3 SW2.1 SW2.2 SW2.4 SW3.1 SW3.2 SW3.4 TR1.5 TR1.6 U1.49 U4.4 U4.9 U5.10 U5.17 U5.48 U5.55 U5.58 U5.64 U5.66 U5.80 U5.114 U6.1 U7.6 U7.9 U8.1 U8.5 U8.7 U8.10 U8.11 U8.16 U9.1 U9.5 U9.10 U9.11 U9.13 U9.16 U10.7 U10.9 U10.10 U10.11 U10.12 U10.16 U11.1 U11.3 U11.9 U11.12 U11.17 Y2.2 Y2.4 Y3.2 Y3.4(NC_4)
VDDC: C43.1 C44.1 C45.1 U5.87(VDDC#87) U5.115
VDDR: C8.1 C9.1 C16.1 L1.2 U1.45 U1.48
VDDS: C3.1 C4.1 C5.1 C6.1 C7.1 FL1.1 R1.2 U1.13 U1.22 U1.34 U1.44
BP_RESET: J2.11 R52.2
CC1190_RFIO: C15.2 FL2.2 R153.2
CC1190_VDD: C27.1 C28.1 C29.1 C161.2 C217.1 L21.1 L131.2 L161.2 L163.2 R151.1
CC1310_RESET: C20.1 CR8.2 P4.12 P5.10 R1.1 R51.2 R52.1 U1.35
CC1310_RXD: J1.7 P4.16 U1.7
CC1310_SWO: J2.9 P4.2 U1.28
CC1310_TCK: CR8.6 P4.8 P5.4 R47.2 U1.25
CC1310_TMS: CR8.7 P4.10 P5.2 R46.2 U1.24
CC1310_TXD: J1.5 P4.14 U1.8
CC1310_VDD: C30.1 C216.1 CR8.8(VCC) FL1.2 J1.1 L163.1 P1.1 P4.18 P5.1 P10.3 R2.2 R3.2 R11.2 R59.2 R60.2 U4.8(VCC)
DCDC_SW: L1.1 U1.33
DIO1: J1.20 U1.6
DIO4_SCL: J1.17 R2.1 U1.9
DIO5_SDA: J1.19 R3.1 U1.10
DIO6_RLED: J2.3 P6.2 U1.11
DIO7_GLED: J2.1 P6.4 U1.12
DIO8_MISO: J2.14 U1.14 U4.2
DIO9_MOSI: J2.12 U1.15(DIO_9) U4.5
DIO10_SCLK: J1.13 U1.16 U4.6
DIO11_CS: J2.6 U1.17
DIO12: J2.4 U1.18
DIO13_BTN1: J2.16 R56.2 U1.19
DIO14_BTN2: J2.18 R55.2 U1.20
DIO15: J2.20 U1.21
DIO16_TDO: CR8.5 P4.4 P5.6 R48.2 U1.26
DIO17_TDI: CR8.3 P4.6 P5.8 R49.2 U1.27
DIO19_CTS: J2.7 U1.29
DIO20_FLASH_CS: J2.5 R11.1 U1.30 U4.1
DIO21: J1.15 U1.31
DIO22: J1.9 U1.32
DIO23_ANALOG: J1.3 U1.36
DIO24_ANALOG: J1.11 U1.37
DIO25_ANALOG: J1.6 U1.38
DIO26_ANALOG: J1.8 U1.39
DIO27_ANALOG: J1.10 U1.40
DIO28_CC1190_HGM: J1.12 R66.1 U1.41
DIO29_CC1190_LNA_EN: J1.14 R71.1 U1.42
DIO30_CC1190_PA_EN: J1.16 R81.1 U1.43
IRSTN: P8.10 R20.2
ITCK: P8.4 U5.100
ITDI: P8.8 U5.98
ITDO: P8.6 U5.97
ITMS: P8.2 U5.99
LP_RESET: J2.10 R51.1
USB_DM: CR6.5 J6.2 U5.93
USB_DP: CR6.4 J6.3 U5.94
USB_ID: CR6.2 J6.4 R19.1
USB_VBUS: C48.1 CR6.6 J6.1(VCC) P4.19 R22.2 R152.1 U7.1 U7.2 U7.8
V-SENSE: C53.1 C55.1 C57.1 CR7.8(VCC) P7.1 P10.2 U8.2(VCCB) U9.2(VCCB) U10.2(VCCB)
XDS_RESET: R58.1 U5.40 U10.1 U10.6
XDS_RESET_LS: CR7.2 P4.11 P7.10 R57.2 U10.15
XDS_RX: U5.33 U8.8
XDS_RX_LS: P4.13 R61.2 U8.13
XDS_SWO: U5.25 U8.9
XDS_SWO_LS: P4.1 R62.2 U8.12
XDS_TCK: U5.35 U9.6
XDS_TCK_LS: CR7.6 P4.7 P7.4 U9.15
XDS_TDI: U5.38 U9.7
XDS_TDI_LS: CR7.3 P4.5 P7.8 U9.14
XDS_TDO: U5.37 U9.9
XDS_TDO_LS: CR7.5 P4.3 P7.6 R63.2 U9.12
XDS_TMS: U5.36 U10.8
XDS_TMS_DIR: U5.24 U10.5
XDS_TMS_LS: CR7.7 P4.9 P7.2 R65.2 U10.13
XDS_TX: U5.34 U8.6
XDS_TX_LS: P4.15 U8.15
XDS_VCC: C35.1 C36.1 C37.1 C38.1 C39.1 C40.1 C41.1 C42.1 C47.1 C49.1 C52.1 C54.1 C56.1 P4.17 P8.1 P10.1 R17.2 R18.2 R27.1 R30.2 R31.2 R33.2 R39.1 R58.2 U5.7 U5.8 U5.16 U5.26 U5.28 U5.39 U5.47 U5.51 U5.52 U5.69 U5.79 U5.90 U5.101 U5.113 U5.122 U7.3 U7.4(OUT#4) U8.3 U8.4 U9.3 U9.4 U10.3 U10.4
N949215: R17.1 R20.1 R21.1 U5.70
N949243: R30.1 U5.60
N949263: C47.2 R33.1 R34.2 U7.5
N949375: R28.2 U5.59
N949517: R22.1 R24.1 U5.1
N949687: C34.1 U5.89 Y3.3
N949695: C33.1 U5.88 Y3.1
N950083: C32.1 C50.1 R18.1 U5.9 U6.3
N950235: R19.2 U5.95
N951001: R39.2 U5.63
N951013: R29.1 U5.61
N951017: R27.2 U5.62
N952443: C46.1 R31.1 U5.68
N1004371: R23.2 U5.3
N1004534: R25.2 U5.4
N1013277: U1.46 Y2.3
N1013919: C15.1 TR1.1(UBP)
N1014101: C17.1 U1.4 Y1.1
N1014113: C18.1 U1.5 Y1.2
N1018952: U1.47 Y2.1
N1031635: CR6.1 J6.M1 J6.M2 R32.2
N1105722: CR1.2 R15.1
N1105771: CR2.2 R14.1
N1105824: P6.1 R14.2
N1106228: P6.3 R15.2
N1176544: J2.13 R46.1
N1176548: J2.15 R47.1
N1176568: J2.17 R48.1
N1177007: J2.19 R49.1
N1288065: R55.1 SW2.3
N1288098: R56.1 SW1.4
N1384129: R57.1 SW3.3
N1393569: C19.1 U1.23
N1442334: R59.1 U4.3
N1442341: R60.1 U4.7
N1462615: R81.2 U11.8
N1462623: R71.2 U11.7
N1462627: C213.2 C214.2 U11.4
N1462755: C215.1 L21.2 L25.1 U11.2
N1462771: C131.2 L131.1 U11.13
N1462879: L161.1 U11.16
N1462923: C210.1 L25.2
N1463021: C214.1 L26.2
N1463025: C24.1 C212.2 C215.2 L26.1 L27.1
N1463037: C213.1 U11.5
N1463305: C24.2 C25.1 L24.1 L27.2
N1463467: C219.2 L111.2 R154.2 R155.1
N1463499: C111.1 FL2.5(OUT) L111.1 R153.1
N1463655: R151.2 U11.15(VDD_PA2)
N1486885: C59.1 R152.2 U5.96
N1492721: A1.1 A2.1 L24.2 R158.2
N1607579: C218.2 R154.1 R156.1
N1607593: C218.1 U11.11
N1607716: R141.1 U11.14
N1608859: P12.1 R13.1
N1608868: P11.1 R157.1
N1608876: R13.2 R157.2 R158.1
N1616867: A2.2 A3.1 ANT1.1
N1639516: TR1.4 U1.1
N1639598: TR1.3 U1.2
N1639697: TR1.2 U1.3
N1666431: C219.1 U11.10
N10367920: CR5.2 R25.1
N10368080: CR4.2 R23.1
N14625751: R66.2 U11.6

Pads without a net: CR7 1; CR8 1; FIDU1 1; FIDU2 1; FIDU3 1; FIDU4 1; FIDU5 1; FIDU6 1; J1 18; J2 8; LBL1 1; P5 7; P7 7; P8 7; U5 2 5 6 11 12 13 14 15 18 19 20 21 22 23 27 29 30 31 32 41 42 43 44 45 46 49 50 53 54 56 57 65 67 71 72 73 74 75 76 77 78 81 82 83 84 85 86 91 92 102 103 104 105 106 107 108 109 110 111 112 116 117 118 119 120 121 123 124 125 126 127 128; U6 2 4 5; U7 7; U8 14; U9 8; U10 14

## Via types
v1: diameter 0.4, hole 0.2, TOP to BOTTOM, 679 vias
v2: diameter 0.5, hole 0.201, TOP to BOTTOM, 28 vias

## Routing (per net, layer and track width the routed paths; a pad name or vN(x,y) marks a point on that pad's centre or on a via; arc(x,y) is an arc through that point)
+5V: length 58.7
  L3 w0.5: P4.20 14,77.42 14.01,77.41 14.01,73.55 J1.2 7.38,70 2.3,70 0.9,68.6 0.9,38 3.48,35.42 P2.1
GND: length 218.4
  TOP w0.15: 31.05,45 U11.9 31.48,44.25 ; 6.4,36.88 P2.2 ; P2.2 6.4,39.04 ; P2.2 7.48,37.96 ; P2.2 5.32,37.96 ; P4.22 12.54,78.62 ; P4.22 11.46,77.54 ; P4.22 10.39,78.62 ; P4.22 11.46,79.7 ; 51.02,40.5 P1.3 ; P1.3 52.1,39.42 ; P1.3 53.18,40.5 ; P1.3 52.1,41.58 ; P4.21 12.54,81.16 ; P4.21 10.39,81.16 ; P4.21 11.46,82.24 ; P4.21 11.46,80.08 ; 55.6,114.45 MH4.1 ; MH4.1 53.45,116.6 ; MH4.1 57.75,116.6 ; 27.4,44.85 C131.1 26.4,44.85 ; P2.3 7.48,40.5 ; P2.3 6.4,41.58 ; P2.3 6.4,39.42 ; P2.3 5.32,40.5 ; P1.2 53.18,37.96 ; P1.2 52.1,36.88 ; P1.2 52.1,39.04 ; P1.2 51.02,37.96 ; 24.2,41.05 C161.1 ; C161.1 24.7,40.54 ; C161.1 25.2,41.05 ; 1.9,81.6 MH5.1 ; MH5.1 4.1,81.6 ; MH5.1 3,82.7 ; MH5.1 3,80.5 ; J2.2 52.12,69.54 ; J2.2 53.2,68.46 ; J2.2 51.05,68.46 ; J2.2 52.12,67.38 ; v1(20.4,84.07) U8.16 19.91,84.61 U8.1 ; 29.1,45 U11.12 28.67,44.25 ; U9.1 28,84.69 27.91,84.6 U9.16 v1(28.4,84.07) ; 27.3,38.33 C27.2 26.3,38.33 ; 25.1,38.33 C29.2 24.1,38.33 ; 7.85,65.92 J1.4 ; J1.4 8.92,65.38 ; J1.4 10,65.92 ; U10.16 v1(24.4,84.07)
  TOP w0.2: v1(29.15,56.45) 29.72,56.45 TR1.6 ; v1(29.15,57) TR1.5
  TOP w0.3: v1(26.5,49.2) 26.5,49.2 R156.2 27.3,49.2 27.3,48.45 v1(27.25,48.4) ; 31.5,30.6 31.15,30.25 v1(31.15,29.35) ; v1(28.95,53.27) FL2.3 ; FL2.3 28.85,54.1 v1(28.1,54.1) ; FL2.3 v1(28.95,55.2) ; v1(26.5,50.3) R155.2 27.3,50.3 27.3,51.1 v1(27.25,51.15) ; v1(31.35,52.53) FL2.6 v1(32.3,51.6) ; v1(23.9,38.35) 24.6,38.35 ; 24.6,38.35 C28.2 ; 24.6,38.35 C29.2 24.6,37.75 ; v1(35.9,34.8) 34.75,34.8 ; v1(26.75,26.5) A3.2 v1(27.55,27.25) 27.53,27.23 ; v1(32.1,49.5) 32.1,50.28 C111.2 v1(32.95,50.3) ; 26.8,38.35 27.4,38.35 v1(27.6,38.15) ; 26.8,38.35 C28.2 ; 26.8,38.35 C27.2 26.8,37.75 ; FL2.1 31.35,55.15 v1(31.45,55.25) ; FL2.1 v1(31.35,53.27) ; FL2.1 31.45,54.1 v1(32.3,54.1) ; U11.17 30.4,42.07 U11.3 30.4,39.85 v1(30.6,39.65) ; U11.17 29.1,43.38 U11.12 ; U11.17 29.1,41.43 U11.1 v1(28.5,40.55) ; U11.17 31.05,43.38 U11.9 ; v1(34.8,40.55) 35.15,40.9 v1(35.9,40.9) ; v1(28.1,51.6) FL2.4 v1(28.95,52.53) ; v1(24.8,45.3) 24.55,45.55 v1(24.55,46.35) ; v1(19.1,40.85) 20.1,40.85 ; C28.2 25.7,37.75 ; v1(25,42.95) R141.2 26,42.95 ; v1(24.5,29.4) 24.5,30.45 ; 20.1,34.85 20.05,34.8 v1(19.1,34.8) ; 29.7,29.4 29.7,30.4
  TOP w0.4: v1(30.7,32.25) C25.2 30.7,33.05 ; v1(30.6,35.05) C212.1 v1(31.5,35.95) ; v1(35.62,37.82) 34.47,37.82 v1(34.4,37.75) ; A1.2 v1(33.15,26.5) ; 27.6,35.95 v1(27.6,35.05) ; 27.6,35.95 v1(27.6,36.85) ; 27.6,35.95 C210.2 v1(26.8,35.95) ; 30.7,33.05 v1(31.5,33.05) ; 30.7,33.05 v1(29.9,33.05) ; v1(27.47,29.68) 27.47,30.78 ; v1(19.32,37.82) 20.68,37.82 ; SC1.3 34.3,31 34.5,31.2 v1(34.5,31.45) ; v1(27.47,45.97) 28.55,45.97 28.95,45.57 v1(28.95,45.1) ; v1(19.4,45.9) 20.45,44.85 ; 34.7,45 35.55,45.85 v1(35.55,45.9) v1(34.6,45.9) v1(33.6,45.9) 31.9,45.9 v1(31.15,45.15) ; v1(19.4,29.75) 20.9,31.25
  TOP w0.5: J6.5 12.7,112.6
  L2 w0.15: P4.22 11.46,79.7 ; P4.22 11.46,77.54 ; P4.22 12.54,78.62 ; P4.22 10.39,78.62 ; 10.39,81.16 P4.21 ; P4.21 11.46,82.24 ; P4.21 11.46,80.08 ; P4.21 12.54,81.16 ; 52.1,39.42 P1.3 ; P1.3 51.02,40.5 ; P1.3 53.18,40.5 ; P1.3 52.1,41.58 ; J1.4 10,65.92 ; J1.4 8.92,67 ; J1.4 8.92,64.84 ; J1.4 7.85,65.92 ; MH3.1 4.95,116.6 ; MH3.1 2.8,114.45 ; MH3.1 0.65,116.6 ; 5.32,40.5 P2.3 ; P2.3 6.4,39.42 ; P2.3 6.4,41.58 ; P2.3 7.48,40.5 ; P1.2 52.1,39.04 ; P1.2 53.18,37.96 ; P1.2 51.02,37.96 ; P1.2 52.1,36.88 ; 5.32,37.96 P2.2 ; P2.2 6.4,36.88 ; P2.2 6.4,39.04 ; P2.2 7.48,37.96 ; J2.2 52.12,69.54 ; J2.2 51.05,68.46 ; J2.2 52.12,67.38 ; J2.2 53.2,68.46 ; MH5.1 3,82.7 ; MH5.1 3,80.5 ; MH5.1 1.9,81.6 ; MH5.1 4.1,81.6 ; MH4.1 57.75,116.6 ; MH4.1 53.45,116.6 ; MH4.1 55.6,114.45
  BOTTOM w0.15: P1.2 52.1,39.04 ; P1.2 52.1,36.88 ; P1.2 53.18,37.96 ; P1.2 51.02,37.96 ; P2.2 6.4,39.04 ; P2.2 6.4,36.88 ; P2.2 7.48,37.96 ; P2.2 5.32,37.96 ; MH5.1 4.1,81.6 ; MH5.1 3,82.7 ; MH5.1 3,80.5 ; MH5.1 1.9,81.6 ; 1.18,118.22 MH3.1 0.65,116.6 ; P4.21 12.54,81.16 ; P4.21 11.46,82.24 ; P4.21 11.46,80.08 ; P4.21 10.39,81.16 ; P2.3 7.48,40.5 ; P2.3 6.4,41.58 ; P2.3 6.4,39.42 ; P2.3 5.32,40.5 ; 52.12,67.38 J2.2 ; J2.2 53.2,68.46 ; J2.2 51.05,68.46 ; J2.2 52.12,69.54 ; J1.4 10,65.92 ; J1.4 8.92,67 ; J1.4 8.92,64.84 ; J1.4 7.85,65.92 ; P1.3 53.18,40.5 ; P1.3 52.1,41.58 ; P1.3 52.1,39.42 ; P1.3 51.02,40.5 ; 11.46,77.54 P4.22 ; P4.22 12.54,78.62 ; P4.22 10.39,78.62 ; P4.22 11.46,79.7
  vias: v1(1,32.3) v1(1,31) v1(1,26.6) v1(1.1,36.8) v1(1.3,70.2) v1(1.4,95) v1(1.6,96.5) v1(1.6,91.6) v1(1.9,41) v1(2.1,111.28) v1(2.1,108.74) v1(2.2,27.45) v1(2.3,98.4) v1(2.3,38.2) v1(2.4,48) v1(2.4,46.9) v1(2.4,45.8) v1(2.4,44.7) v1(2.4,43.7) v1(2.6,77.2) v1(2.9,40.2) v1(3.37,107.47) v1(3.4,55) v1(3.4,54) v1(3.4,53) v1(3.5,52) v1(3.6,85.7) v1(3.6,60.1) v1(3.55,27) v1(3.7,59.1) v1(3.7,58.1) v1(3.7,57.1) v1(4,62) v1(4.8,106.3) v1(4.9,63.8) v1(4.9,61.2) v1(4.9,47.5) v1(4.9,26.5) v1(5.1,95.3) v1(5.3,110.9) v1(5.9,73.1) v1(6,111.9) v1(6,74.9) v1(6.4,86) v1(6.6,76.7) v1(7,26.5) v1(7.1,75.1) v1(7.4,64.8) v1(7.4,28.3) v1(7.5,106.6) v1(7.8,77.4) v1(8,75.9) v1(8.4,31) v1(8.5,112.3) v1(8.7,76.8) v1(9,89.2) v1(9,40) v1(9.2,79.8) v1(9.3,26.5) v1(9.7,41.3) v1(9.9,35.7) v1(10,108.3) v1(10.1,61.25) v1(10.2,42.7) v1(10.3,71.9) v1(10.5,76.7) v1(10.5,41) v1(10.7,109.3) v1(10.7,65.7) v1(10.8,105.2) v1(10.8,29) v1(11.2,42.75) v1(11.2,26.5) v1(11.3,86.1) v1(11.4,65.4) v1(11.6,68.6) v1(11.7,49.2) v1(11.8,102) v1(11.8,89.2) v1(11.8,73.1) v1(11.85,42.15) v1(12.2,60.5) v1(12.3,105.6) v1(12.4,58.1) v1(12.6,42.75) v1(12.8,49.2) v1(12.9,56.3) v1(13,26.5) v1(13.2,66.2) v1(13.15,61.2) v1(13.4,69.4) v1(13.5,112.2) v1(13.5,39.3) v1(13.8,111.3) v1(13.9,71.6) v1(13.9,52.4) v1(14,46.6) v1(14.2,55.7) v1(14.3,106.6) v1(14.5,112.3) v1(14.75,42.05) v1(14.85,28.25) v1(14.95,30) v1(14.9,26.5) v1(15,72.6) v1(15,71.3) v1(14.98,46.7) v1(15.1,49.4) v1(15.15,57.85) v1(15.4,53.3) v1(15.51,72.73) v1(15.6,65.6) v1(15.65,41.25) v1(15.8,111.4) v1(16,55.3) v1(16.2,57) v1(16.3,85.8) v1(16.6,66.6) v1(16.65,42) v1(16.9,49.2) v1(16.9,47.37) v1(17.3,102) v1(17.5,30.9) v1(17.6,105.4) v1(17.7,70.7) v1(17.8,85.7) v1(17.8,73.2) v1(17.9,95.3) v1(17.9,26.5) v1(18,98.2) v1(18.1,48) v1(18.3,106.4) v1(18.5,55) v1(18.5,49.08) v1(18.8,110.1) v1(19,61.65) v1(19.2,85.3) v1(19.25,76.6) v1(19.3,69.2) v1(19.3,48.2) v1(19.4,26.5) v1(20.2,67.7) v1(20.2,56.45) v1(20.4,42.95) v1(20.4,41.55) v1(20.7,87.9) v1(20.7,71) v1(20.7,51.45) v1(20.7,48.4) v1(20.8,108.8) v1(21,61.6) v1(21,36.25) v1(21.1,26.5) v1(21.2,77.3) v1(21.3,95.1) v1(21.3,56.6) v1(21.5,66.7) v1(21.5,42.35) v1(21.5,29.4) v1(21.55,59.25) v1(21.6,55.8) v1(21.7,83.5) v1(21.7,60.3) v1(21.8,111.8) v1(21.8,61.25) v1(21.9,44.25) v1(22.2,32.45) v1(22.15,30) v1(22.3,93.2) v1(22.3,55.1) v1(22.3,48.7) v1(22.3,37.65) v1(22.4,58.8) v1(22.6,108.7) v1(22.6,100.7) v1(22.6,44.85) v1(22.7,98.7) v1(22.7,26.5) v1(22.8,41.85) v1(22.8,40.75) v1(22.8,29.4) v1(23,35.95) v1(23.2,56.7) v1(23.2,43.05) v1(23.3,61.6) v1(23.3,53.3) v1(23.3,34.05) v1(23.4,55.1) v1(23.6,66.9) v1(23.7,67.8) v1(23.65,47.7) v1(23.8,61.9) v1(23.9,30.45) v1(24,69.5) v1(24,41.05) v1(24.3,32.75) v1(24.4,67.1) v1(24.4,61.7) v1(24.4,26.5) v1(24.6,37.65) v1(24.7,40.35) v1(24.85,54.05) v1(24.8,53.5) v1(24.9,87.5) v1(24.9,76.32) v1(25,60.9) v1(25.1,89.9) v1(25.3,111.8) v1(25.3,30.35) v1(25.35,28.25) v1(25.45,54.4) v1(25.4,41.45) v1(25.4,33.75) v1(25.5,107.2) v1(25.5,47.1) v1(25.5,35.75) v1(25.6,117.4) v1(25.7,102.9) v1(25.7,97.9) v1(25.7,37.65) v1(25.9,59.5) v1(26,32.1) v1(26.1,61.5) v1(26.1,44.85) v1(26.1,40.15) v1(26.5,55.1) v1(26.6,57.7) v1(26.6,56.5) v1(26.6,29.3) v1(26.65,83.42) v1(26.8,37.65) v1(27,33.35) v1(27.1,53.3) v1(27.2,57.7) v1(27.3,85.5) v1(27.4,92.2) v1(27.6,44.85) v1(27.8,40.35) v1(27.9,33.05) v1(28.3,57.3) v1(28.5,44.25) v1(28.6,30.75) v1(28.9,69.4) v1(28.9,31.85) v1(29.15,70.3) v1(29.4,43.05) v1(29.4,42.45) v1(29.4,41.75) v1(29.6,31.75) v1(29.7,69.3) v1(29.7,68.8) v1(30.1,43.05) v1(30.1,42.45) v1(30.1,41.75) v1(30.2,69.3) v1(30.2,68.8) v1(30.5,88.1) v1(30.7,73.95) v1(30.7,38.85) v1(30.7,38.05) v1(30.8,43.05) v1(30.8,42.45) v1(30.8,41.75) v1(31.35,28.3) v1(31.4,71.35) v1(31.6,44.25) v1(31.7,40.75) v1(31.8,87.3) v1(32,30.75) v1(32.1,35.05) v1(32.3,44.2) v1(32.5,35.85) v1(32.7,46.95) v1(32.7,31.55) v1(32.8,39.75) v1(33.1,38.15) v1(33.2,36.55) v1(33.35,70.8) v1(33.35,69.65) v1(33.3,29.75) v1(33.5,48.8) v1(33.5,39.15) v1(33.6,87) v1(33.65,52.2) v1(33.7,32.25) v1(33.85,51.25) v1(33.95,50) v1(33.9,35.85) v1(34.1,26.5) v1(34.2,118.2) v1(34.2,41.05) v1(34.5,41.85) v1(34.5,39.15) v1(34.55,51.65) v1(34.65,46.6) v1(35.1,48.8) v1(35.35,51.15) v1(35.3,49.6) v1(35.3,46.98) v1(35.3,43.95) v1(35.4,26.5) v1(35.5,54) v1(35.6,87.6) v1(35.6,42.35) v1(35.6,32.95) v1(35.6,29.75) v1(35.75,45.3) v1(35.8,39.35) v1(36,40.05) v1(36.4,54.1) v1(36.4,50.7) v1(36.45,42) v1(36.5,103.6) v1(36.5,49.4) v1(36.55,66) v1(36.6,41.15) v1(36.6,26.5) v1(36.8,42.85) v1(36.85,42.8) v1(37.1,74.15) v1(37.1,44.05) v1(37.2,66.5) v1(37.6,76.5) v1(37.6,54.5) v1(37.6,53.6) v1(37.75,47.2) v1(37.75,26.5) v1(37.9,65.9) v1(38.1,59.8) v1(38.15,42.8) v1(38.15,25.45) v1(38.7,64) v1(38.7,59.2) v1(38.7,46.1) v1(38.8,80.5) v1(38.95,26.5) v1(39,42.9) v1(39,24.6) v1(39.1,83.5) v1(39.2,90.1) v1(39.15,39.05) v1(39.4,53.6) v1(39.6,86.3) v1(39.6,82.4) v1(40.04,75.34) v1(40,23.75) v1(40.1,54.28) v1(40.3,42.5) v1(40.8,50.1) v1(40.9,44.1) v1(40.95,22.6) v1(41,61.5) v1(41,45.6) v1(41.1,118) v1(41.2,24.9) v1(41.3,27.6) v1(41.6,50) v1(41.7,43.1) v1(41.85,21.65) v1(41.9,47.5) v1(42.2,52.6) v1(42.2,49.1) v1(42.6,83.3) v1(42.64,73.56) v1(42.6,27.6) v1(42.8,24.8) v1(43,51.1) v1(43,21.61) v1(43.1,39.5) v1(43.2,43.2) v1(43.15,36.35) v1(43.9,30.7) v1(43.95,29.05) v1(43.95,27.55) v1(43.9,24.2) v1(44,23.1) v1(44.2,46) v1(44.45,70.15) v1(44.45,42.05) v1(44.8,37.9) v1(44.9,90.5) v1(45.3,41.45) v1(45.7,51.9) v1(45.7,49.4) v1(45.9,43.7) v1(46.2,85) v1(46.38,73.1) v1(46.5,70.7) v1(47.2,80.1) v1(47.2,70.8) v1(47.6,87.3) v1(47.8,43.5) v1(47.9,32.5) v1(48,117.6) v1(48.2,75.8) v1(48.28,30.69) v1(48.28,21.61) v1(48.7,71.2) v1(50,34) v1(50,32.4) v1(50.2,76.6) v1(50.4,70.6) v1(50.7,46.4) v1(50.8,88.7) v1(52.08,81.5) v1(52.3,80.4) v1(52.3,76.6) v1(52.6,81.4) v1(52.6,74.9) v1(52.8,75.8) v1(52.9,77.5) v1(52.95,73.85) v1(53.3,79.9) v1(53.65,87.35) v1(53.8,85) v1(53.9,56.8) v1(54.1,80.4) v1(54.4,42.6) v1(54.5,46.3) v1(54.7,39.1) v1(54.76,80.83) v1(55.1,89.5) v1(55.4,40.6) v1(55.6,44) v1(55.8,80.6) v1(56.1,79.4) v1(56.3,80.9) v1(56.65,86.9) v1(56.8,45.4) v1(56.9,94.6) v1(56.9,85.3) v1(56.9,43.2) v1(56.9,41.6) v1(57,69.3) v1(57,36.5) v1(57.1,101.2) v1(57.15,67.1) v1(57.1,65.1) v1(57.1,63.3) v1(57.1,61.4) v1(57.15,60) v1(57.15,57.1) v1(57.15,54.3) v1(57.15,51.1) v1(57.15,48.3) v1(57.2,105.7) v1(57.3,112.2) v1(57.3,81) v2(13.2,110) v2(13.2,109.1) v2(13.2,108.2) v2(30.6,64.1) v2(30.6,63.1) v2(30.6,62.1) v2(30.6,61.1) v2(30.6,60.1) v2(31.6,64.1) v2(31.6,63.1) v2(31.6,62.1) v2(31.6,61.1) v2(31.6,60.1) v2(32.6,64.1) v2(32.6,63.1) v2(32.6,62.1) v2(32.6,61.1) v2(32.6,60.1) v2(33.6,64.1) v2(33.6,63.1) v2(33.6,62.1) v2(33.6,61.1) v2(33.6,60.1) v2(34.6,64.1) v2(34.6,63.1) v2(34.6,62.1) v2(34.6,61.1) v2(34.6,60.1)
VDDC: length 16.2
  TOP w0.2: U5.87 8.9,96.2 7.3,94.6 U5.115 2.5,94.6 C43.1 C44.1 C45.1
VDDR: length 28.7
  TOP w0.3: v1(28.4,59) 28.1,58.7 28.1,58.3 ; 28.1,58.3 28.2,58.3 ; 28.1,58.3 C9.1 28.2,58.3 ; 28.2,58.3 28.58,58.3 ; 28.58,58.3 29.18,58.9 ; 28.58,58.3 28.6,58.3 29.18,58.88 U1.48 ; U1.45 28.12,60.82 C16.1 27.6,60.47 27.17,60.9 v1(25.8,60.9)
  TOP w0.4: L1.2 C8.1
  TOP w0.5: v1(25.8,69.55) 27.75,71.5 30.28,71.5 31.4,70.38 C8.1
  L3 w0.3: v1(25.8,60.9) 25.8,60.42 27.22,59 v1(28.4,59)
  L3 w0.4: v1(25.8,69.55) 25.2,68.95 25.2,61.5 v1(25.8,60.9)
VDDS: length 41.4
  TOP w0.3: C3.1 v1(37.2,59.8) ; C3.1 36.25,59.2 U1.13 ; C3.1 37.08,59.32 ; C7.1 30,67.19 30.9,66.29 ; C7.1 C6.1 28.2,67.2 27.9,66.9 R1.2 27.9,66.5 ; C7.1 30.9,66.3 U1.34 ; v1(38,64.7) 37.83,64.7 37.3,64.17 C4.1 37.12,63.82 U1.22
  TOP w0.4: U1.44 28.38,61.32 28.2,61.5 C5.1 v1(27.6,62) ; v1(25.2,71) FL1.1 ; 28.1,67.1 v1(27.6,67.6)
  L3 w0.4: 36.85,65.45 28,65.45 27.6,65.85 ; 36.85,65.45 37.23,65.07 37.63,65.07 ; 36.85,65.45 37.25,65.45 37.63,65.07 ; 37.63,65.07 v1(38,64.7) ; v1(27.6,62) 27.6,65.85 ; 27.6,65.85 v1(27.6,67.6) 27.6,69.3 v1(25.9,71)
  L3 w0.5: v1(25.9,71) v1(25.2,71)
  L3 w0.6: v1(38,64.7) 37.2,63.9 v1(37.2,59.8)
BP_RESET: length 27.3
  TOP w0.15: J2.11 50.94,54.4 54.3,54.4 54.7,54.8 54.7,69.2 50.2,73.7 R52.2
CC1190_RFIO: length 2
  TOP w0.3: C15.2 29.73,55.47 30.1,55.1 30.1,54.25 FL2.2 R153.2
CC1190_VDD: length 12.6
  TOP w0.3: 24.9,43.95 L131.2 v1(24,43.95) ; C161.2 24.68,41.95 ; 24.68,41.95 R151.1 26,40.97 L161.2 ; 24.68,41.95 v1(24,41.95)
  TOP w0.4: v1(24,43.95) v1(24,44.45)
  TOP w0.5: v1(23.7,39.25) C29.1 C28.1 C27.1 27.9,39.25 L21.1 ; v1(17.8,43.7) v1(16.95,43.7) C217.1 L163.2
CC1310_RESET: length 70.6
  TOP w0.15: v1(18.75,72.7) 18.75,66.4 19.45,65.7 C20.1 R1.1 28.35,65.7 28.95,66.3 29.98,66.3 30.4,65.88 U1.35 ; v1(46.9,73.6) 47,73.7 R52.1 ; 47.9,72.2 R51.2 R52.1 ; R52.1 47.9,73.72 45.78,75.84 P5.10
  TOP w0.3: v1(38.7,73.7) 38.7,73.82 38.65,73.88 38.65,74.05 38.6,74.1 CR8.2
  L3 w0.15: v1(18.75,72.7) v1(24.16,72.7) ; v1(24.16,72.7) 24.16,77.59 ; v1(24.16,72.7) 26.87,72.7 26.92,72.65 27.28,72.65 27.33,72.7 43.66,72.7 43.69,72.68 46.56,72.68 46.59,72.7 46.75,72.7 46.9,72.85 v1(46.9,73.6) 46.51,73.99 38.99,73.99 v1(38.7,73.7) ; 24.16,77.59 P4.12 ; 24.16,77.59 24.2,77.56
CC1310_RXD: length 83.9
  TOP w0.15: v1(27.1,73.07) 27.1,73.65 26.78,73.97 v1(22.5,73.97) 22.1,73.97 21.97,74.1 10.5,74.1 4,67.6 4,63.22 J1.7 ; v1(43.87,73.1) 43.87,72.7 43.9,72.66 43.9,71.7 v1(44.2,71.4) 44.2,70.78 43.75,70.32 43.75,60.15 40.3,56.7 34.15,56.7 32.9,57.95 U1.7
  L3 w0.15: P4.16 22.5,75.2 v1(22.5,73.97) ; v1(27.1,73.07) 27.5,73.07 27.58,73 37.2,73 37.3,73.1 v1(43.87,73.1)
CC1310_SWO: length 38.1
  TOP w0.15: v1(44.3,61.5) v1(44.3,63.9) ; 33.9,65.55 U1.28 v1(33.9,67.1) 33.9,75.97 v1(34.4,76.47) ; v1(46.93,58.3) 46.93,58.83 46.99,58.89 46.99,60.18 46.97,60.2 v1(46.97,60.6)
  L3 w0.15: v1(44.3,61.5) 46,61.5 46.9,60.6 v1(46.97,60.6) ; v1(34.4,76.47) 36.71,76.47 36.86,76.62 P4.2 ; v1(44.3,63.9) 41.73,63.9 38.24,67.38 34.19,67.38 v1(33.9,67.1) ; v1(46.93,58.3) J2.9
CC1310_TCK: length 58.6
  TOP w0.15: U1.25 v1(35.4,66.6) 35.4,70.3 35.05,70.65 35.05,75.67 35.43,76.05 35.43,76.32 v1(36.1,77) 37.8,77 39.75,78.95 40.91,78.95 41.97,77.89 P5.4 41.97,76.95 41.42,76.4 39.8,76.4 39.4,76.8 38.9,76.8 38.6,76.5 CR8.6 ; v1(46.5,63.4) 46.5,56.78 45,55.28 45,51.43 45.7,50.72 R47.2
  L3 w0.15: v1(35.4,66.6) 35.8,67 38.2,67 41.8,63.4 v1(46.5,63.4) ; v1(36.1,77) 35.7,77 35.6,76.9 30.96,76.9 P4.8
CC1310_TMS: length 54.9
  TOP w0.15: v1(47.1,67.1) 47.1,66.5 47.4,66.2 47.4,57.25 45.7,55.55 R46.2 ; U1.24 36.12,65.18 35.9,65.4 v1(35.9,69.12) 35.9,70.5 35.35,71.05 35.35,75.2 v1(36.2,76.05) 37.3,76.05 37.45,75.9 CR8.7 38.1,76.5 39.3,77.7 P5.2
  L3 w0.15: v1(47.1,67.1) 40.62,67.1 38.6,69.12 v1(35.9,69.12) ; v1(36.2,76.05) 33.85,76.05 33.4,76.5 28.82,76.5 P4.10
CC1310_TXD: length 81.3
  TOP w0.15: J1.5 4.79,64.97 4.79,65.19 5.33,65.73 5.33,66.35 5.95,66.97 6.57,66.97 7.87,68.27 7.87,68.9 8.49,69.51 9.11,69.51 13.4,73.8 21.2,73.8 21.5,73.5 v1(25.5,73.5) ; v1(43.4,70.9) 43.4,60.22 40.18,57 34.35,57 33.4,57.95 U1.8 ; v1(36.2,71.49) v1(36.2,73.5)
  L3 w0.15: v1(36.2,73.5) v1(25.5,73.5) 25.5,79.35 25.18,79.67 22.67,79.67 P4.14 ; v1(36.2,71.49) 43.22,71.49 43.4,71.3 v1(43.4,70.9)
CC1310_VDD: length 186
  TOP w0.2: R11.2 39.52,51.8 R59.2
  TOP w0.3: U4.8 C30.1 ; C30.1 v1(38.8,55) ; C30.1 39.4,55.72 R60.2 ; v1(21.7,71.1) 21.8,71 ; v1(40.2,72) 40.35,72 40.7,72.35 P5.1 38.39,73.1 38.1,73.39 38.1,73.4 37.6,73.9 37.6,74.9 CR8.8 ; v1(38.6,51.6) 39.32,51.6 R11.2
  TOP w0.4: 21.8,71 FL1.2 ; v1(2.6,42.1) 3.15,42.65 3.75,42.05 ; v1(20.72,72.09) v1(21.7,71.1)
  TOP w0.5: v1(8.3,42.7) v1(8.95,43.35) 9.3,43.7 C216.1 L163.1
  L3 w0.3: 21.3,71.5 v1(21.3,71.51)
  L3 w0.4: v1(21.7,71.1) 21.3,71.5 ; 38.97,51.23 38.97,48.55 45.52,42 45.53,42 45.85,41.68 45.85,41.67 P1.1 ; v1(2.6,42.1) 2.5,42.1 ; v1(21.3,71.51) 21.26,71.55 21.25,71.55 v1(20.72,72.09)
  L3 w0.5: v1(8.3,42.7) 7.7,42.1 v1(2.6,42.1) 1.55,43.15 1.55,63.63 J1.1 7.61,67.24 13.34,67.24 16.54,70.44 16.54,72.56 ; 51.2,74 51.2,73.95 57.75,67.4 57.75,41.07 P1.1 52.08,35.4 ; 51.2,74 49.2,72 v1(40.2,72) 36.53,72 36.45,72.09 v1(20.72,72.09) 17.01,72.09 16.54,72.56 ; 51.2,74 51.2,77.32 P10.3 ; v1(38.8,55) 38.8,52.58 38.6,52.38 v1(38.6,51.6) 39.01,51.19 ; 16.54,72.56 P4.18
DCDC_SW: length 1.9
  TOP w0.3: 31.4,66.35 31.4,66.35 ; 31.4,66.35 U1.33 ; 31.4,66.35 L1.1
DIO1: length 34.4
  TOP w0.15: J1.20 9.97,46.65 9.97,49.17 v1(11,50.2) ; v1(34.18,56.03) 33.72,56.49 33.72,56.63 32.4,57.95 U1.6 ; v1(22.5,50.1) v1(24.95,52.55)
  L3 w0.15: v1(22.5,50.1) 12.1,50.1 12,50.2 v1(11,50.2) ; v1(34.18,56.03) 32.85,54.7 27.1,54.7 v1(24.95,52.55)
DIO4_SCL: length 99.9
  TOP w0.15: R2.1 3.8,43.3 3.8,45.56 J1.17 4.26,48.14 2,50.4 2,68.4 6.8,73.2 6.82,73.2 9.22,75.6 32.7,75.6 v1(33.1,75.2) ; v1(37.7,70.33) 37.3,70.33 36.65,70.98 36.65,74.85 v1(37.1,75.3) ; U1.9 33.9,57.95 34.55,57.3 40.05,57.3 43.01,60.26 43.01,69.82 42.97,69.86 v1(42.97,70.26)
  L3 w0.15: v1(33.1,75.2) 37,75.2 v1(37.1,75.3) ; v1(42.97,70.26) 42.57,70.26 42.51,70.33 v1(37.7,70.33)
DIO5_SDA: length 98.1
  TOP w0.15: v1(37.1,73.5) 37.1,71.5 v1(37.6,71) ; U1.10 34.4,57.95 34.75,57.6 39.93,57.6 42.51,60.19 42.51,70.51 42.6,70.6 v1(42.6,71) ; R3.1 4.4,42.7 4.4,43.62 J1.19 7.43,46.65 7.43,48.57 6.61,49.4 3.6,49.4 2.3,50.7 2.3,68.2 9.4,75.3 32.3,75.3 32.9,74.7 v1(32.9,74)
  L3 w0.15: v1(42.6,71) v1(37.6,71) ; v1(37.1,73.5) 36.6,74 v1(32.9,74)
DIO6_RLED: length 54.7
  TOP w0.15: U1.11 34.9,58.05 35.05,57.9 35.53,57.9 35.68,58.05 v1(36.45,58.05) 39.68,58.05 42,60.38 v1(42,68.2)
  L3 w0.15: P6.2 18.4,59.29 18.4,57.3 24.97,50.72 32.13,50.72 32.8,51.4 32.8,54 36.45,57.65 v1(36.45,58.05) ; J2.3 47,68.5 42.3,68.5 v1(42,68.2)
DIO7_GLED: length 43.6
  TOP w0.15: v1(41.5,68.8) 41.5,60.3 39.8,58.6 v1(36.15,58.6) U1.12
  L3 w0.15: v1(41.5,68.8) 48.22,68.8 48.56,68.46 J2.1 ; v1(36.15,58.6) 33.45,55.9 23.3,55.9 19.69,59.51 P6.4
DIO8_MISO: length 23.8
  TOP w0.15: v1(43.7,54.3) 43.7,53.9 43.2,53.4 41,53.4 40.7,53.1 U4.2 ; v1(39,59.8) 38.57,60.22 37.02,60.22 36.62,59.82 ; 36.62,59.82 36.62,59.82 ; 36.62,59.82 U1.14
  L3 w0.15: J2.14 51.04,54.3 v1(43.7,54.3) 43.7,55.1 v1(39,59.8)
DIO9_MOSI: length 21
  TOP w0.15: U1.15 36.7,60.32 36.9,60.53 39.28,60.53 v1(39.6,60.2) ; U4.5 41.7,56.35 42.27,56.93 v1(42.68,56.93)
  L3 w0.15: J2.12 50.99,56.9 46.2,56.9 45.9,56.6 v1(45.2,56.6) 44.88,56.93 v1(42.68,56.93) 42.22,57.38 42.22,57.59 v1(39.6,60.2)
DIO10_SCLK: length 92.3
  TOP w0.15: U4.6 41.2,56.72 44.78,60.3 45.22,60.3 ; 45.22,60.3 45.22,60.3 45.22,67.88 45.2,67.9 v1(45.2,74.7) ; 45.22,60.3 v1(45.14,60.39) ; v1(31.7,74.5) 31.5,74.7 9.72,74.7 3,67.97 3,56.6 J1.13 ; U1.16 39.82,60.82 39.9,60.9 v1(40.3,60.9)
  L3 w0.15: v1(40.3,60.9) 40.81,60.39 v1(45.14,60.39) ; v1(45.2,74.7) 44.8,74.7 44.7,74.6 32.2,74.6 32.1,74.5 v1(31.7,74.5)
DIO11_CS: length 22
  TOP w0.15: U1.17 v1(38.2,61.32) ; J2.6 53.5,62 53.5,60.5 52.5,59.5 v1(50.4,59.5)
  L3 w0.15: v1(50.4,59.5) 47.4,59.5 45.9,61 40.8,61 40.48,61.32 v1(38.2,61.32)
DIO12: length 19.7
  TOP w0.15: U1.18 38.6,61.82 38.6,61.83 v1(39,61.83) ; J2.4 51,64.8 48.65,64.8 48.2,64.35 48.2,61.98 48.12,61.9 v1(48.12,61.5)
  L3 w0.15: v1(39,61.83) 40.72,61.83 40.82,61.93 47.1,61.93 47.52,61.5 v1(48.12,61.5) 48.2,61.5
DIO13_BTN1: length 88.6
  TOP w0.15: v1(55.2,68.95) 55.2,66.5 55.1,66.4 55.1,53.66 J2.16 ; v1(40.8,69.3) 40.8,68.9 41,68.7 41,63.8 39.53,62.32 U1.19 ; v1(36.6,75.62) 35.7,74.72 35.7,71.32 v1(37,70.03) ; 6.8,73.6 6.82,73.62 ; 6.82,73.62 R56.2 ; 6.82,73.62 9.1,75.9 27,75.9 27.2,76.1 v1(27.6,76.1)
  L3 w0.15: v1(37,70.03) 37.4,70.03 37.53,69.9 40.2,69.9 v1(40.8,69.3) 41.12,69.62 52.99,69.62 53.65,68.95 v1(55.2,68.95) ; v1(36.6,75.62) 33.47,75.62 33,76.1 v1(27.6,76.1)
DIO14_BTN2: length 46.4
  TOP w0.15: J2.18 56.1,52.12 v1(56.1,62.2) 56.1,70.14 55.64,70.6 R55.2 ; v1(40.25,64.35) 40.25,63.65 39.43,62.82 U1.20
  L3 w0.15: v1(56.1,62.2) 49.28,62.2 48.58,62.9 41.7,62.9 v1(40.25,64.35)
DIO15: length 39.6
  TOP w0.15: U1.21 39.12,63.32 v1(39.6,63.8) ; J2.20 56.62,50.09 56.62,58.41 56.7,58.5 56.7,61.16 56.63,61.23 v1(56.63,61.64)
  L3 w0.15: v1(39.6,63.8) 41.12,62.28 48.32,62.28 48.7,61.9 55.8,61.9 56.06,61.64 v1(56.63,61.64)
